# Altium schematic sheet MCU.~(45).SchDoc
size A3; SheetNumber: 10; SheetTotal: 11
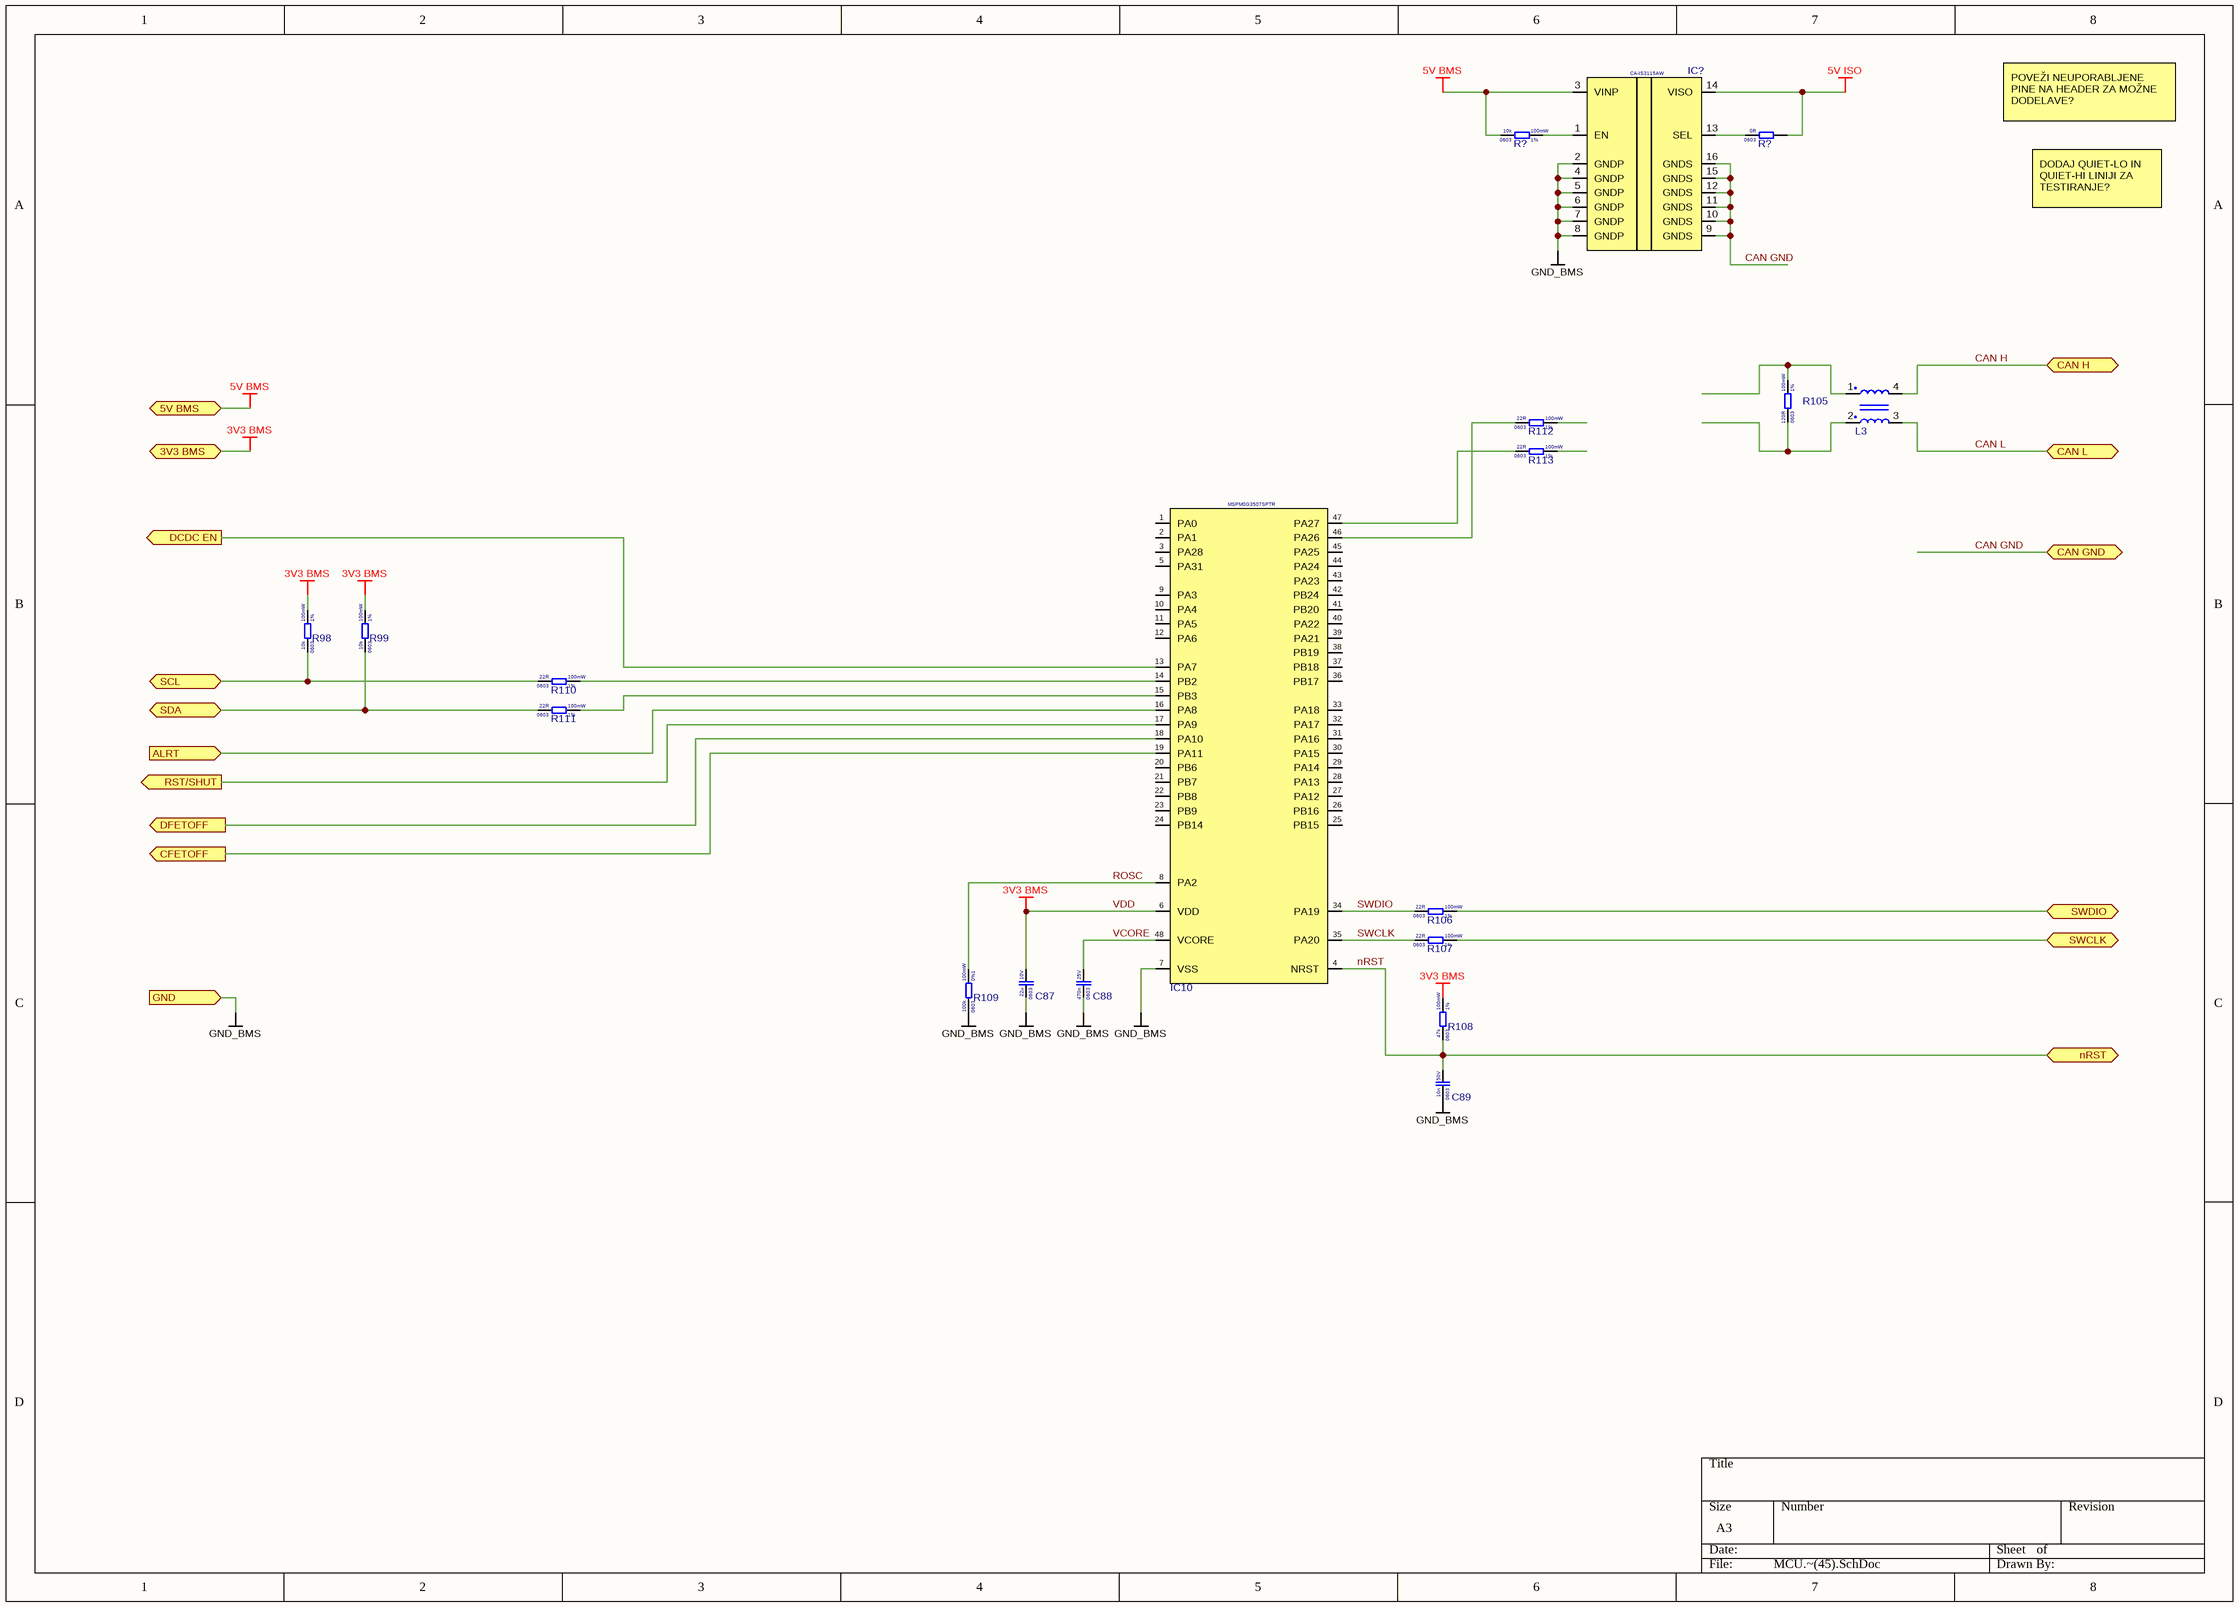
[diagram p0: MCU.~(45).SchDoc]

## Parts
(Parts that share a designator on the sheet are numbered #1, #2 ... from top to bottom, then left to right.)
C87  Voltage Rating: 10V  Case Code (Imperial): 0603  Capacitance: 22u  [CAP 0603]  (hidden comment: CGA0603X5R226M100JT)
C88  Voltage Rating: 25V  Case Code (Imperial): 0603  Capacitance: 470n  [CAP 0603]  (hidden comment: CL10B474KA8NNNC)
C89  Voltage Rating: 50V  Case Code (Imperial): 0603  Capacitance: 10n  [CAP 0603]  (hidden comment: 0603B103K500NT)
IC10  MSPM0G3507SPTR  [LQFP-48]
IC?  CA-IS3115AW  [SOIC-16-WB]
L3  ACM2012-900-2P-T002  [ACM2012-900-2P-T002]  (value not drawn)
R98  Resistance Tolerance: 1%  Resistance: 10k  Power Rating: 100mW  Case Code (Imperial): 0603  [RES_0603]  (hidden comment: 0603WAF1002T5E)
R99  Resistance Tolerance: 1%  Resistance: 10k  Power Rating: 100mW  Case Code (Imperial): 0603  [RES_0603]  (hidden comment: 0603WAF1002T5E)
R105  Resistance Tolerance: 1%  Resistance: 120R  Power Rating: 100mW  Case Code (Imperial): 0603  [RES_0603]  (hidden comment: 0603WAF1200T5E)
R106  Resistance Tolerance: 1%  Resistance: 22R  Power Rating: 100mW  Case Code (Imperial): 0603  [RES_0603]  (hidden comment: 0603WAF220JT5E)
R107  Resistance Tolerance: 1%  Resistance: 22R  Power Rating: 100mW  Case Code (Imperial): 0603  [RES_0603]  (hidden comment: 0603WAF220JT5E)
R108  Resistance Tolerance: 1%  Resistance: 47k  Power Rating: 100mW  Case Code (Imperial): 0603  [RES_0603]  (hidden comment: 0603WAF4702T5E)
R109  Resistance Tolerance: 0%1  Resistance: 100k  Power Rating: 100mW  Case Code (Imperial): 0603  [RES_0603]  (hidden comment: RT0603BRD07100KL)
R110  Resistance Tolerance: 1%  Resistance: 22R  Power Rating: 100mW  Case Code (Imperial): 0603  [RES_0603]  (hidden comment: 0603WAF220JT5E)
R111  Resistance Tolerance: 1%  Resistance: 22R  Power Rating: 100mW  Case Code (Imperial): 0603  [RES_0603]  (hidden comment: 0603WAF220JT5E)
R112  Resistance Tolerance: 1%  Resistance: 22R  Power Rating: 100mW  Case Code (Imperial): 0603  [RES_0603]  (hidden comment: 0603WAF220JT5E)
R113  Resistance Tolerance: 1%  Resistance: 22R  Power Rating: 100mW  Case Code (Imperial): 0603  [RES_0603]  (hidden comment: 0603WAF220JT5E)
R?#1  Resistance Tolerance: 1%  Resistance: 10k  Power Rating: 100mW  Case Code (Imperial): 0603  [RES_0603]  (hidden comment: 0603WAF1002T5E)
R?#2  Resistance: 0R  Case Code (Imperial): 0603  [RES_0603]  (hidden comment: 0603WAF0000T5E)

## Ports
3V3 BMS (bidir, see BMS[4B]), 5V BMS (bidir, see BMS[4B]), ALRT (in, see BMS[4B], BQ76952 BMS[7C]), CAN GND (bidir, see BMS[4B], BMS[8B]), CAN H (bidir, see BMS[4B], BMS[8B], ESD system side[2B]), CAN L (bidir, see BMS[4B], BMS[8B], ESD system side[2B]), CFETOFF (out, see BMS[4B], BQ76952 BMS[7C]), DCDC EN (out, see BMS[4B]), DFETOFF (out, see BMS[4B], BQ76952 BMS[7C]), GND (in, see BMS[4C], BQ76952 BMS[1D]), nRST (bidir, see BMS[4B], BMS[8B]), RST/SHUT (out, see BMS[4B], BQ76952 BMS[7C]), SCL (bidir, see BMS[4C], BMS[8C], BQ76952 BMS[7C]), SDA (bidir, see BMS[4C], BMS[8C], BQ76952 BMS[7C]), SWCLK (bidir, see BMS[4B], BMS[8B]), SWDIO (bidir, see BMS[4B], BMS[8B])

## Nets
5V BMS: IC?.3(VINP) R?#1.1 ; port 5V BMS
5V ISO: IC?.14(VISO) R?#2.2
GND_BMS: C87.1 C88.1 C89.1 IC10.7(VSS) IC?.2(GNDP) IC?.4(GNDP) IC?.5(GNDP) IC?.6(GNDP) IC?.7(GNDP) IC?.8(GNDP) R109.1 ; port GND
VDD: C87.2 IC10.6(VDD) R98.2 R99.2 R108.2 ; port 3V3 BMS  [also labelled 3V3 BMS]
ALRT: IC10.16(PA8) ; port ALRT
CAN GND: IC?.9(GNDS) IC?.10(GNDS) IC?.11(GNDS) IC?.12(GNDS) IC?.15(GNDS) IC?.16(GNDS) ; port CAN GND
CAN H: L3.4 ; port CAN H
CAN L: L3.3 ; port CAN L
CFETOFF: IC10.19(PA11) ; port CFETOFF
DCDC EN: IC10.13(PA7) ; port DCDC EN
DFETOFF: IC10.18(PA10) ; port DFETOFF
nRST: C89.2 IC10.4(NRST) R108.1 ; port nRST
ROSC: IC10.8(PA2) R109.2
RST/SHUT: IC10.17(PA9) ; port RST/SHUT
SCL: R98.1 R110.1 ; port SCL
SDA: R99.1 R111.1 ; port SDA
SWCLK: IC10.35(PA20) R107.1
SWCLK: R107.2 ; port SWCLK  [a separate net that carries the same name]
SWDIO: IC10.34(PA19) R106.1
SWDIO: R106.2 ; port SWDIO  [a separate net that carries the same name]
VCORE: C88.2 IC10.48(VCORE)
NetIC10_14: IC10.14(PB2) R110.2
NetIC10_15: IC10.15(PB3) R111.2
NetIC10_46: IC10.46(PA26) R112.1
NetIC10_47: IC10.47(PA27) R113.1
NetIC?_1: IC?.1(EN) R?#1.2
NetIC?_13: IC?.13(SEL) R?#2.1
NetL3_1: L3.1 R105.2
NetL3_2: L3.2 R105.1

Not connected (* = marked no-connect by the designer): IC10 1(PA0) 2(PA1) 3(PA28) 5(PA31) 9(PA3) 10(PA4) 11(PA5) 12(PA6) 20(PB6) 21(PB7) 22(PB8) 23(PB9) 24(PB14) 25(PB15) 26(PB16) 27(PA12) 28(PA13) 29(PA14) 30(PA15) 31(PA16) 32(PA17) 33(PA18) 36(PB17) 37(PB18) 38(PB19) 39(PA21) 40(PA22) 41(PB20) 42(PB24) 43(PA23) 44(PA24) 45(PA25); R112 2; R113 2

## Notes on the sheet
- POVEŽI NEUPORABLJENE PINE NA HEADER ZA MOŽNE DODELAVE?
- DODAJ QUIET-LO IN QUIET-HI LINIJI ZA TESTIRANJE?

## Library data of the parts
C87 = CGA0603X5R226M100JT: Cap 22uF 10V 0603 X5R; Manufacturer: HRE
C88 = CL10B474KA8NNNC: Cap 470nF 25V 0603 X7R; Manufacturer: Samsung
C89 = 0603B103K500NT: Cap 10nF 50V 0603 X7R; Manufacturer: FH
IC10 = MSPM0G3507SPTR: MCU MSPM0G3507SPTR LQFP-48; Manufacturer: Texas Instruments
IC? = CA-IS3115AW: DCDC Module Isolated 5Vin 5Vout 1.5W SOIC-16-WB; Manufacturer: Chipanalog
L3 = ACM2012-900-2P-T002: CMC 90R@100MHz 190mR 400mA 50V; Manufacturer: TDK
R98 R99 R?#1 = 0603WAF1002T5E: Res 10k 0603 1% 100mW 75V; Manufacturer: Uni-Royal
R105 = 0603WAF1200T5E: Res 120R 0603 1% 100mW 75V; Manufacturer: Uni-Royal; Manufacturer Part Number: 0603WAF5101T5E
R106 R107 R110-R113 = 0603WAF220JT5E: Res 22R 0603 1% 100mW 75V; Manufacturer: Uni-Royal
R108 = 0603WAF4702T5E: Res 47k 0603 1% 100mW 75V; Manufacturer: Uni-Royal
R109 = RT0603BRD07100KL: Res 100k 0603 0.1% 100mW 75V 25ppm; Manufacturer: YAGEO
R?#2 = 0603WAF0000T5E: Res 0R 0603 1% 100mW 75V; Manufacturer: UNI-ROYAL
